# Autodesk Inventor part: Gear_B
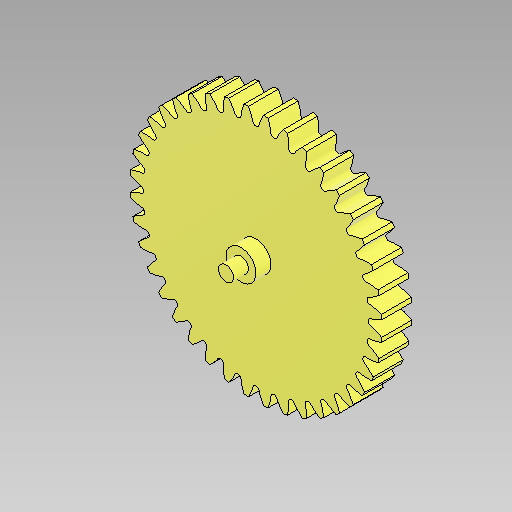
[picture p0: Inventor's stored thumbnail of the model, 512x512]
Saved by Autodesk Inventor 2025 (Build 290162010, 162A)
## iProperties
Created: 2024-10
Part Number: Gear_B
Material: Generic
Document SubType Name: Modeling
Designer: Dennis
Mass: 50.4311 g
Surface Area: 151.33 cm^2
Volume: 50.4311 cm^3
Density: 1 g/cm^3
Appearance: Smooth - Yellow
Author: Dennis
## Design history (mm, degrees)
sketch "Sketch1"
  geometry: C1 r 37.5 at (0, 0) reference; C2 r 37.588 at (0, 0) reference; C3 r 40 at (0, 0) reference; A1 r 42 centre (0, 0) between (-2.536, 41.923) and (2.536, 41.923) reference; 38 further points
  constraints: 4 centre point, 2 point on circle, 83 other
extrude "Extrusion1" join sketch "Sketch1" distance "d0" = 10 (= FaceWidth); taper "d1" = 0 deg
extrude "Extrusion2" cut sketch "Sketch1" extent not by distance; stored distance "d2" = 0; taper "d3" = 0 deg
sketch "Sketch2"
  geometry: L1 (0, 0)-(5, 0); L2 (5, 0)-(5, 5); L3 (5, 5)-(2.5, 5); L4 (2.5, 5)-(2.5, 10); L5 (2.5, 10)-(0, 10); L6 (0, 10)-(0, 0)
  constraints: 12 end point, 5 perpendicular, 1 horizontal, 1 parallel
  dimensions: "d7" = 5 diameter of L4 L6; "d8" = 10 diameter of L2 L6; "d9" = 5 distance of L1.end L2.end
revolve "Revolution1" sketch "Sketch2" stored, may be unused: angle "d10" = 90 deg
body "Solid1"
pattern_circular "Circular Pattern1" dims angle "d5" = 360 deg
other parameters: "Module" = 2 [user parameter], "PressureAngle" = 20 deg [user parameter], "UnitProfileClearance" = 2.5 [user parameter], "UnitRoundRadius" = 3.5 [user parameter], "HeadDiameter" = 84 [user parameter], "RootDiameter" = 75 [user parameter], "BaseDiameter" = 75.17541 [user parameter], "FaceWidth" = 10 [user parameter; used in 1 equation term], "HelixAngle" = 0 [user parameter], "UnitCorrection" = 0 [user parameter], "UnitAddendumModification" = 0 [user parameter], "CircularPitch" = 36 deg [user parameter], "UnitBacklashShift" = 0 [user parameter], "TotalToolShift" = 0 [user parameter], "IsInternal" = 0 [user parameter]
